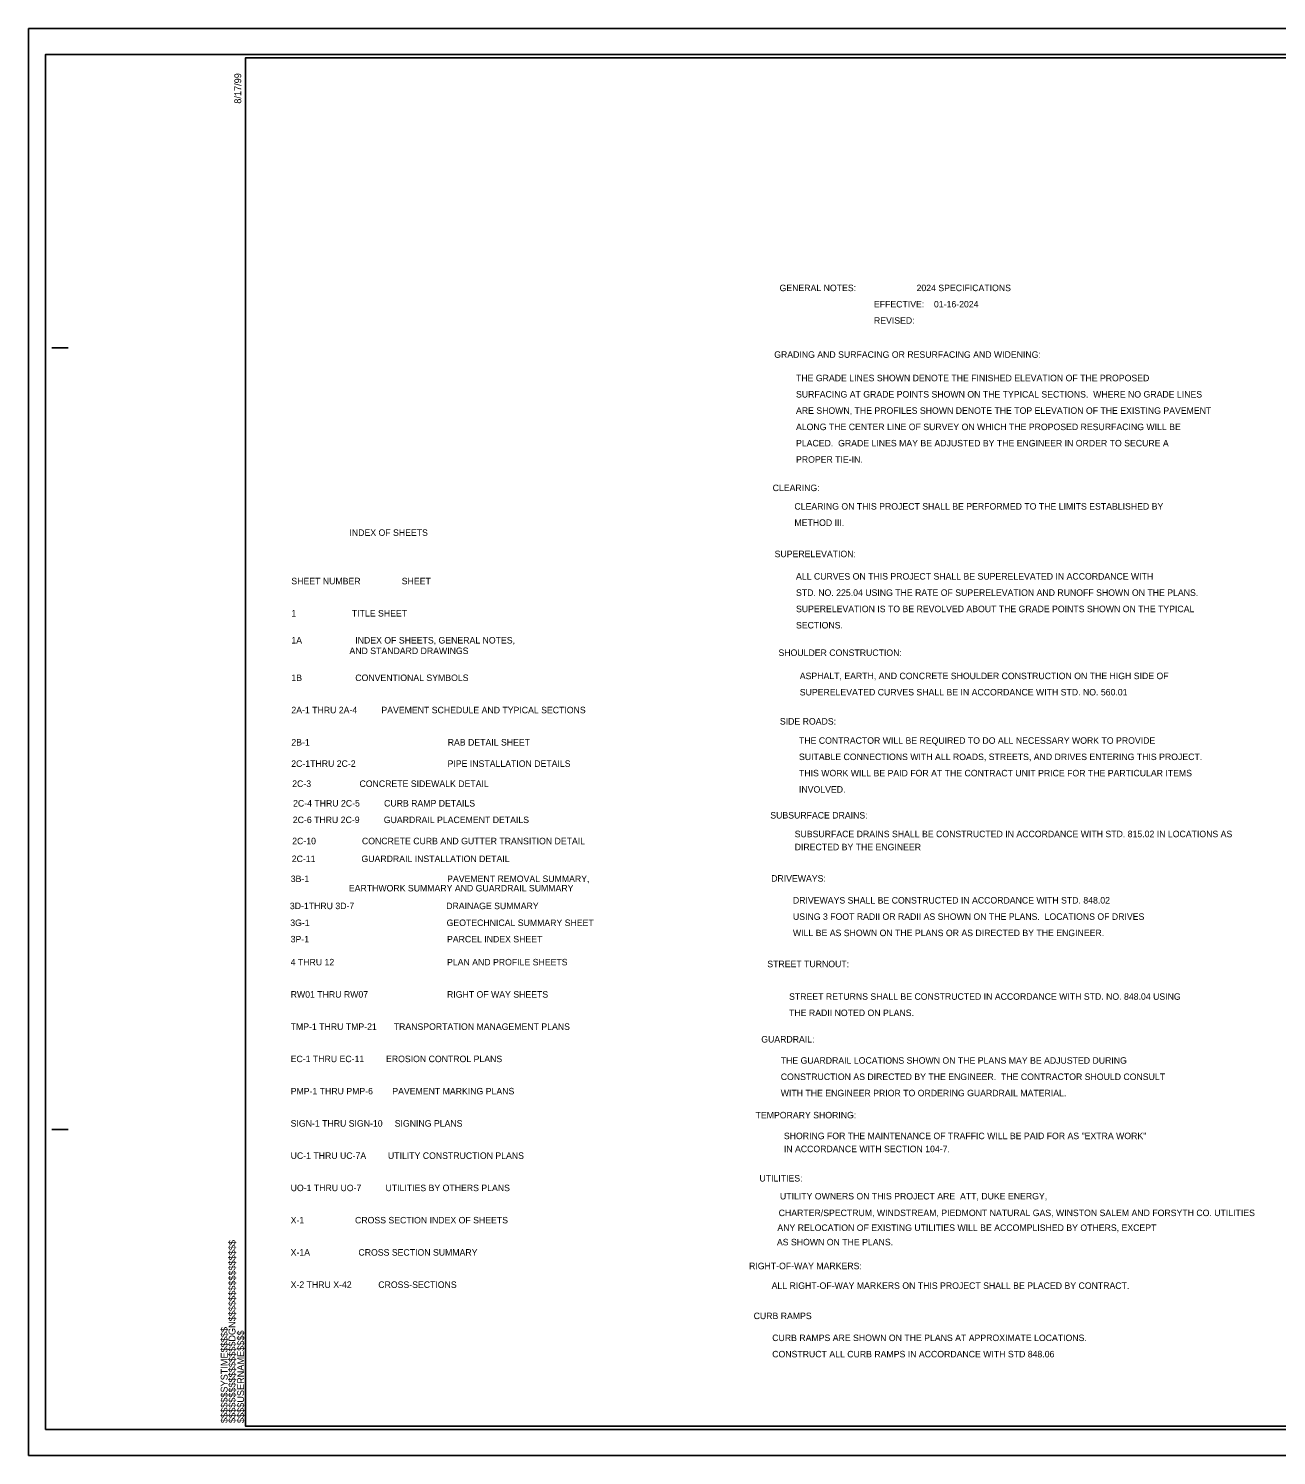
# Model space of a CAD drawing. Extents: x 1773483.6 to 1773517.3, y 886704.6 to 886726.5.
# Drawn here: x 1773483.6 to 1773502.76, y 886704.6 to 886726.5 of the extents above; entities that cross this region are included whole.
import ezdxf

# ---------------------------------------------------------------- set-up
doc = ezdxf.new("R2010")
doc.units = 0
for name, color, linetype in [('Sheet Cutting Line CELL', 7, 'Continuous'), ('Sheet Data Text CELL', 7, 'Continuous'), ('Sheet Plan CELL', 7, 'Continuous'), ('Sheet Plot Border Inside CELL', 7, 'Continuous'), ('Sheet Plot Border Outside CELL', 7, 'Continuous')]:
    doc.layers.add(name, color=color, linetype=linetype)

msp = doc.modelspace()

# ---------------------------------------------------------------- linework, layer by layer
at = {"layer": 'Sheet Cutting Line CELL'}
for p, q in [((1773517.272, 886726.499), (1773483.602, 886726.499)), ((1773483.602, 886726.499), (1773483.602, 886704.599)), ((1773483.602, 886704.599), (1773517.272, 886704.599))]:
    msp.add_line(p, q, dxfattribs=at)
at = {"layer": 'Sheet Plan CELL'}
for p, q in [((1773486.932, 886726.049), (1773486.932, 886726.049)), ((1773483.962, 886721.599), (1773484.212, 886721.599)), ((1773483.962, 886709.599), (1773484.212, 886709.599)), ((1773486.932, 886705.049), (1773486.932, 886705.049))]:
    msp.add_line(p, q, dxfattribs=at)
msp.add_lwpolyline([(1773516.932, 886726.049), (1773486.932, 886726.049), (1773486.932, 886705.049), (1773516.932, 886705.049)], close=True, dxfattribs=at)
at = {"layer": 'Sheet Plot Border Inside CELL'}
msp.add_lwpolyline([(1773483.862, 886704.999), (1773517.182, 886704.999), (1773517.182, 886726.099), (1773483.862, 886726.099)], close=True, dxfattribs=at)
at = {"layer": 'Sheet Plot Border Outside CELL'}
msp.add_lwpolyline([(1773483.602, 886704.599), (1773517.272, 886704.599), (1773517.272, 886726.499), (1773483.602, 886726.499)], close=True, dxfattribs=at)

# ---------------------------------------------------------------- texts
at = {"layer": 'Sheet Data Text CELL'}
for s, p in [('                        INDEX OF SHEETS ', (1773487.637, 886718.712)), ('SHEET NUMBER                 SHEET   ', (1773487.637, 886717.969)), ('1                       TITLE SHEET', (1773487.637, 886717.474)), ('1A                      INDEX OF SHEETS, GENERAL NOTES,', (1773487.637, 886717.06)), ('                        AND STANDARD DRAWINGS', (1773487.637, 886716.898)), ('1B                      CONVENTIONAL SYMBOLS ', (1773487.637, 886716.484)), ('2A-1 THRU 2A-4          PAVEMENT SCHEDULE AND TYPICAL SECTIONS', (1773487.637, 886715.989)), ('2B-1          ', (1773487.637, 886715.494)), ('RAB DETAIL SHEET', (1773490.037, 886715.494)), ('2C-1THRU 2C-2', (1773487.635, 886715.167)), ('PIPE INSTALLATION DETAILS', (1773490.035, 886715.167)), ('2C-3                    CONCRETE SIDEWALK DETAIL', (1773487.65, 886714.859)), ('2C-4 THRU 2C-5          CURB RAMP DETAILS', (1773487.663, 886714.558)), ('2C-6 THRU 2C-9          GUARDRAIL PLACEMENT DETAILS', (1773487.659, 886714.304)), ('2C-10                   CONCRETE CURB AND GUTTER TRANSITION DETAIL', (1773487.65, 886713.979)), ('2C-11                   GUARDRAIL INSTALLATION DETAIL', (1773487.643, 886713.706)), ('3B-1          ', (1773487.628, 886713.399)), ('PAVEMENT REMOVAL SUMMARY,', (1773490.028, 886713.399)), ('                        EARTHWORK SUMMARY AND GUARDRAIL SUMMARY', (1773487.628, 886713.255)), ('3D-1THRU 3D-7          ', (1773487.614, 886712.983)), ('DRAINAGE SUMMARY', (1773490.014, 886712.983)), ('3G-1          ', (1773487.62, 886712.724)), ('GEOTECHNICAL SUMMARY SHEET', (1773490.02, 886712.724)), ('3P-1          ', (1773487.626, 886712.473)), ('PARCEL INDEX SHEET', (1773490.026, 886712.473)), ('4 THRU 12', (1773487.626, 886712.12)), ('PLAN AND PROFILE SHEETS', (1773490.026, 886712.12)), ('RW01 THRU RW07', (1773487.626, 886711.625)), ('RIGHT OF WAY SHEETS', (1773490.026, 886711.625)), ('TMP-1 THRU TMP-21       TRANSPORTATION MANAGEMENT PLANS', (1773487.626, 886711.13)), ('EC-1 THRU EC-11         EROSION CONTROL PLANS', (1773487.626, 886710.635)), ('PMP-1 THRU PMP-6        PAVEMENT MARKING PLANS', (1773487.626, 886710.14)), ('SIGN-1 THRU SIGN-10     SIGNING PLANS', (1773487.626, 886709.645)), ('UC-1 THRU UC-7A         UTILITY CONSTRUCTION PLANS', (1773487.626, 886709.15)), ('UO-1 THRU UO-7          UTILITIES BY OTHERS PLANS', (1773487.626, 886708.655)), ('X-1                     CROSS SECTION INDEX OF SHEETS', (1773487.626, 886708.16)), ('X-1A                    CROSS SECTION SUMMARY', (1773487.626, 886707.665)), ('X-2 THRU X-42           CROSS-SECTIONS', (1773487.626, 886707.17))]:
    msp.add_text(s, height=0.1, dxfattribs=at).set_placement(p)
at = {"layer": 'Sheet Plan CELL'}
for s, p in [('8/17/99', (1773486.867, 886725.345)), ('$$$$$$$$$$$$$$$$DGN$$$$$$$$$$$$$$$$', (1773486.779, 886705.096)), ('$$$$$$SYSTIME$$$$$', (1773486.658, 886705.096)), ('$$$$USERNAME$$$$', (1773486.911, 886705.096))]:
    msp.add_text(s, height=0.105, rotation=90, dxfattribs=at).set_placement(p)
for s, p in [('GENERAL NOTES:                         2024 SPECIFICATIONS', (1773495.131, 886722.468)), ('                                       EFFECTIVE:    01-16-2024', (1773495.131, 886722.218)), ('                                       REVISED:      ', (1773495.131, 886721.968)), ('GRADING AND SURFACING OR RESURFACING AND WIDENING:  ', (1773495.049, 886721.445)), ('         THE GRADE LINES SHOWN DENOTE THE FINISHED ELEVATION OF THE PROPOSED ', (1773495.049, 886721.085)), ('         SURFACING AT GRADE POINTS SHOWN ON THE TYPICAL SECTIONS.  WHERE NO GRADE LINES ', (1773495.049, 886720.835)), ('         ARE SHOWN, THE PROFILES SHOWN DENOTE THE TOP ELEVATION OF THE EXISTING PAVEMENT ', (1773495.049, 886720.585)), ('         ALONG THE CENTER LINE OF SURVEY ON WHICH THE PROPOSED RESURFACING WILL BE ', (1773495.049, 886720.335)), ('         PLACED.  GRADE LINES MAY BE ADJUSTED BY THE ENGINEER IN ORDER TO SECURE A ', (1773495.049, 886720.085)), ('         PROPER TIE-IN.  ', (1773495.049, 886719.835)), ('CLEARING:  ', (1773495.025, 886719.399)), ('         CLEARING ON THIS PROJECT SHALL BE PERFORMED TO THE LIMITS ESTABLISHED BY ', (1773495.025, 886719.115)), ('         METHOD III.', (1773495.025, 886718.865)), ('SUPERELEVATION:  ', (1773495.055, 886718.385)), ('         ALL CURVES ON THIS PROJECT SHALL BE SUPERELEVATED IN ACCORDANCE WITH', (1773495.049, 886718.041)), ('         STD. NO. 225.04 USING THE RATE OF SUPERELEVATION AND RUNOFF SHOWN ON THE PLANS.', (1773495.049, 886717.791)), ('         SUPERELEVATION IS TO BE REVOLVED ABOUT THE GRADE POINTS SHOWN ON THE TYPICAL ', (1773495.049, 886717.541)), ('         SECTIONS.  ', (1773495.049, 886717.291)), ('SHOULDER CONSTRUCTION:  ', (1773495.114, 886716.869)), ('         ASPHALT, EARTH, AND CONCRETE SHOULDER CONSTRUCTION ON THE HIGH SIDE OF', (1773495.107, 886716.513)), ('         SUPERELEVATED CURVES SHALL BE IN ACCORDANCE WITH STD. NO. 560.01', (1773495.107, 886716.263)), ('SIDE ROADS:  ', (1773495.136, 886715.816)), ('         THE CONTRACTOR WILL BE REQUIRED TO DO ALL NECESSARY WORK TO PROVIDE ', (1773495.095, 886715.521)), ('         SUITABLE CONNECTIONS WITH ALL ROADS, STREETS, AND DRIVES ENTERING THIS PROJECT.  ', (1773495.095, 886715.271)), ('         THIS WORK WILL BE PAID FOR AT THE CONTRACT UNIT PRICE FOR THE PARTICULAR ITEMS ', (1773495.095, 886715.021)), ('         INVOLVED.  ', (1773495.095, 886714.771)), ('SUBSURFACE DRAINS:', (1773494.989, 886714.374)), ('         SUBSURFACE DRAINS SHALL BE CONSTRUCTED IN ACCORDANCE WITH STD. 815.02 IN LOCATIONS AS ', (1773495.029, 886714.087)), ('         DIRECTED BY THE ENGINEER', (1773495.029, 886713.887)), ('DRIVEWAYS:  ', (1773495.002, 886713.405)), ('         DRIVEWAYS SHALL BE CONSTRUCTED IN ACCORDANCE WITH STD. 848.02', (1773495.002, 886713.069)), ('         USING 3 FOOT RADII OR RADII AS SHOWN ON THE PLANS.  LOCATIONS OF DRIVES', (1773495.002, 886712.819)), ('         WILL BE AS SHOWN ON THE PLANS OR AS DIRECTED BY THE ENGINEER.  ', (1773495.002, 886712.569)), ('STREET TURNOUT:  ', (1773494.943, 886712.092)), ('         STREET RETURNS SHALL BE CONSTRUCTED IN ACCORDANCE WITH STD. NO. 848.04 USING ', (1773494.943, 886711.592)), ('         THE RADII NOTED ON PLANS.  ', (1773494.943, 886711.342)), ('GUARDRAIL:  ', (1773494.85, 886710.936)), ('         THE GUARDRAIL LOCATIONS SHOWN ON THE PLANS MAY BE ADJUSTED DURING ', (1773494.815, 886710.611)), ('         CONSTRUCTION AS DIRECTED BY THE ENGINEER.  THE CONTRACTOR SHOULD CONSULT', (1773494.815, 886710.361)), ('         WITH THE ENGINEER PRIOR TO ORDERING GUARDRAIL MATERIAL.', (1773494.815, 886710.111)), ('TEMPORARY SHORING:', (1773494.763, 886709.772)), ('         SHORING FOR THE MAINTENANCE OF TRAFFIC WILL BE PAID FOR AS "EXTRA WORK" ', (1773494.863, 886709.453)), ('         IN ACCORDANCE WITH SECTION 104-7.', (1773494.863, 886709.253)), ('UTILITIES:  ', (1773494.822, 886708.803)), ('         UTILITY OWNERS ON THIS PROJECT ARE  ATT, DUKE ENERGY, ', (1773494.803, 886708.528)), ('         CHARTER/SPECTRUM, WINDSTREAM, PIEDMONT NATURAL GAS, WINSTON SALEM AND FORSYTH CO. UTILITIES', (1773494.783, 886708.272)), ('         ANY RELOCATION OF EXISTING UTILITIES WILL BE ACCOMPLISHED BY OTHERS, EXCEPT ', (1773494.763, 886708.044)), ('         AS SHOWN ON THE PLANS.  ', (1773494.756, 886707.823)), ('RIGHT-OF-WAY MARKERS:  ', (1773494.663, 886707.457)), ('         ALL RIGHT-OF-WAY MARKERS ON THIS PROJECT SHALL BE PLACED BY CONTRACT.  ', (1773494.675, 886707.155)), ('CURB RAMPS', (1773494.733, 886706.691)), ('        CURB RAMPS ARE SHOWN ON THE PLANS AT APPROXIMATE LOCATIONS.', (1773494.721, 886706.354)), ('        CONSTRUCT ALL CURB RAMPS IN ACCORDANCE WITH STD 848.06 ', (1773494.721, 886706.104))]:
    msp.add_text(s, height=0.1, dxfattribs=at).set_placement(p)

doc.saveas('drawing.dxf')
